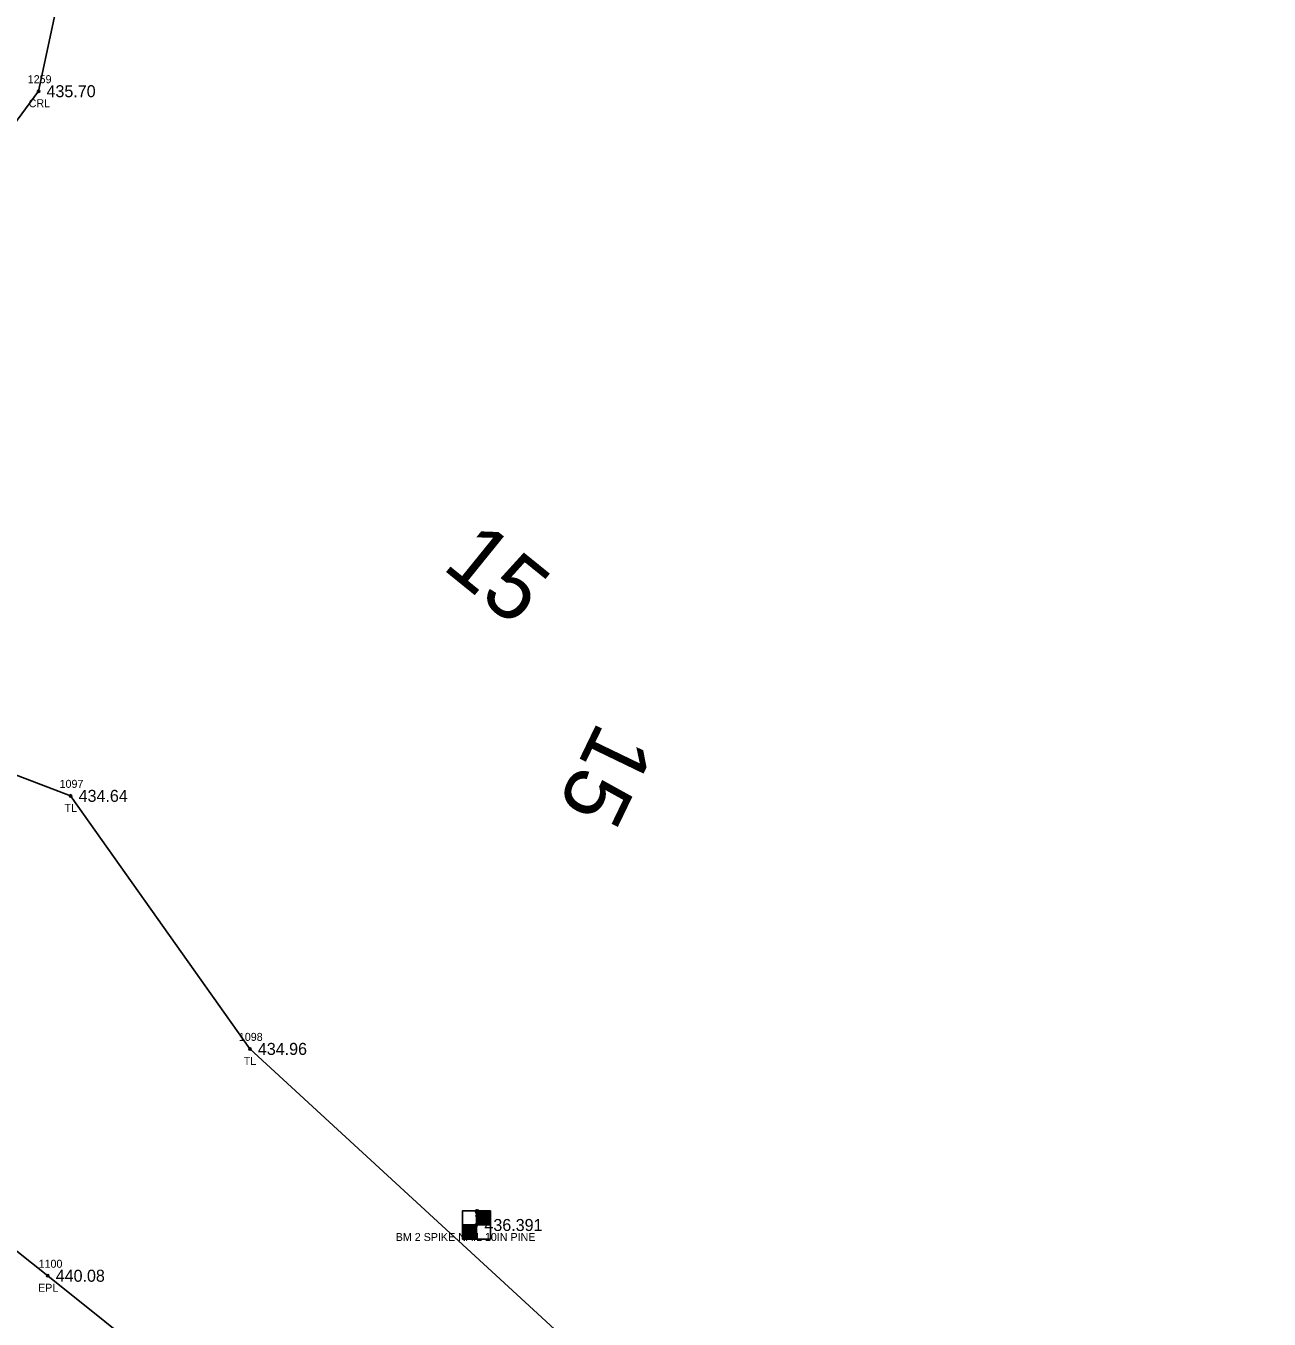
# Model space of a CAD drawing. Extents: x 1611865 to 1617004, y 775289 to 778546.
# Drawn here: x 1614524.5 to 1614679.9, y 777648.2 to 777809.8 of the extents above; entities that cross this region are included whole.
import ezdxf

# ---------------------------------------------------------------- set-up
doc = ezdxf.new("R2010")
doc.units = 0
for name, color, linetype in [('RD_EX_H2O', 7, 'Continuous'), ('RD_EX_H2O_txCode', 7, 'Continuous'), ('RD_EX_Road', 7, 'Continuous'), ('RD_EX_Road_txCode', 7, 'Continuous'), ('RD_EX_TX_H2O_ELEV', 7, 'Continuous'), ('RD_EX_TX_Road_ELEV', 7, 'Continuous'), ('RD_EX_TX_VEG_ELEV', 7, 'Continuous'), ('RD_EX_VEG', 7, 'Continuous'), ('RD_EX_VEG_txCode', 7, 'Continuous'), ('RD_HC_Survey', 7, 'Continuous'), ('RD_HC_Survey_ELEV', 7, 'Continuous'), ('RD_HC_Survey_txCode', 7, 'Continuous'), ('RD_HC_TX_Sta50', 7, 'Continuous'), ('RD_SMD_Locator', 7, 'Continuous')]:
    doc.layers.add(name, color=color, linetype=linetype)

msp = doc.modelspace()

# ---------------------------------------------------------------- linework, layer by layer
at = {"layer": 'RD_EX_H2O'}
msp.add_lwpolyline([(1614612.84, 778001.09), (1614602.8, 777969.59), (1614583.96, 777919.69), (1614574.96, 777902.32), (1614550.82, 777861.38), (1614543.23, 777842.17), (1614528.68, 777813.75), (1614526.1, 777801.65), (1614517.13, 777789.52), (1614510.38, 777774.58), (1614495.52, 777745.97), (1614480.57, 777714.78), (1614474.46, 777705.96), (1614477.93, 777705.13), (1614481.15, 777703.4), (1614481.27, 777700.99), (1614480.97, 777699.74), (1614478.44, 777696.16), (1614475.82, 777697.62), (1614468.32, 777689.25), (1614463.06, 777676.24), (1614459.87, 777668.19), (1614440.89, 777623.61)], dxfattribs=at)
at = {"layer": 'RD_EX_Road'}
msp.add_lwpolyline([(1614484.15, 777687.93), (1614527.25, 777653.67), (1614604.97, 777591.41), (1614629.13, 777572.93), (1614683.14, 777529.85), (1614759.91, 777466.85), (1614838.21, 777403.78), (1614915.19, 777340.18), (1614934.98, 777324.5), (1615070.79, 777214.66)], dxfattribs=at)
at = {"layer": 'RD_EX_VEG'}
msp.add_lwpolyline([(1614491.14, 777728.5), (1614530.11, 777713.62), (1614552.51, 777682.01), (1614626.02, 777614.41), (1614703.99, 777552.85), (1614782.74, 777493.63), (1614860.24, 777426.8), (1615012.81, 777300.37), (1615089.65, 777237.2)], dxfattribs=at)
at = {"layer": 'RD_HC_Survey'}
for p, q in [((1614580.82, 777661.76), (1614580.82, 777658.26)), ((1614580.84, 777661.76), (1614580.84, 777660.01)), ((1614580.87, 777661.76), (1614580.87, 777660.01)), ((1614580.89, 777661.76), (1614580.89, 777660.01)), ((1614580.92, 777661.76), (1614580.92, 777660.01)), ((1614580.94, 777661.76), (1614580.94, 777660.01)), ((1614580.97, 777661.76), (1614580.97, 777660.01)), ((1614580.99, 777661.76), (1614580.99, 777660.01)), ((1614581.01, 777661.76), (1614581.01, 777660.01)), ((1614581.04, 777661.76), (1614581.04, 777660.01)), ((1614581.06, 777661.76), (1614581.06, 777660.01)), ((1614581.09, 777661.76), (1614581.09, 777660.01)), ((1614581.11, 777661.76), (1614581.11, 777660.01)), ((1614581.14, 777661.76), (1614581.14, 777660.01)), ((1614581.16, 777661.76), (1614581.16, 777660.01)), ((1614581.19, 777661.76), (1614581.19, 777660.01)), ((1614581.21, 777661.76), (1614581.21, 777660.01)), ((1614581.24, 777661.76), (1614581.24, 777660.01)), ((1614581.26, 777661.76), (1614581.26, 777660.01)), ((1614581.29, 777661.76), (1614581.29, 777660.01)), ((1614581.31, 777661.76), (1614581.31, 777660.01)), ((1614581.34, 777661.76), (1614581.34, 777660.01)), ((1614581.36, 777661.76), (1614581.36, 777660.01)), ((1614581.39, 777661.76), (1614581.39, 777660.01)), ((1614581.41, 777661.76), (1614581.41, 777660.01)), ((1614581.44, 777661.76), (1614581.44, 777660.01)), ((1614581.46, 777661.76), (1614581.46, 777660.01)), ((1614581.48, 777661.76), (1614581.48, 777660.01)), ((1614581.51, 777661.76), (1614581.51, 777660.01)), ((1614581.53, 777661.76), (1614581.53, 777660.01)), ((1614581.56, 777661.76), (1614581.56, 777660.01)), ((1614581.58, 777661.76), (1614581.58, 777660.01)), ((1614581.61, 777661.76), (1614581.61, 777660.01)), ((1614581.63, 777661.76), (1614581.63, 777660.01)), ((1614581.66, 777661.76), (1614581.66, 777660.01)), ((1614581.68, 777661.76), (1614581.68, 777660.01)), ((1614581.71, 777661.76), (1614581.71, 777660.01)), ((1614581.73, 777661.76), (1614581.73, 777660.01)), ((1614581.76, 777661.76), (1614581.76, 777660.01)), ((1614581.78, 777661.76), (1614581.78, 777660.01)), ((1614581.81, 777661.76), (1614581.81, 777660.01)), ((1614581.83, 777661.76), (1614581.83, 777660.01)), ((1614581.86, 777661.76), (1614581.86, 777660.01)), ((1614581.88, 777661.76), (1614581.88, 777660.01)), ((1614581.91, 777661.76), (1614581.91, 777660.01)), ((1614581.93, 777661.76), (1614581.93, 777660.01)), ((1614581.96, 777661.76), (1614581.96, 777660.01)), ((1614581.98, 777661.76), (1614581.98, 777660.01)), ((1614582, 777661.76), (1614582, 777660.01)), ((1614582.03, 777661.76), (1614582.03, 777660.01)), ((1614582.05, 777661.76), (1614582.05, 777660.01)), ((1614582.08, 777661.76), (1614582.08, 777660.01)), ((1614582.1, 777661.76), (1614582.1, 777660.01)), ((1614582.13, 777661.76), (1614582.13, 777660.01)), ((1614582.15, 777661.76), (1614582.15, 777660.01)), ((1614582.18, 777661.76), (1614582.18, 777660.01)), ((1614582.2, 777661.76), (1614582.2, 777660.01)), ((1614582.23, 777661.76), (1614582.23, 777660.01)), ((1614582.25, 777661.76), (1614582.25, 777660.01)), ((1614582.28, 777661.76), (1614582.28, 777660.01)), ((1614582.3, 777661.76), (1614582.3, 777660.01)), ((1614582.33, 777661.76), (1614582.33, 777660.01)), ((1614582.35, 777661.76), (1614582.35, 777660.01)), ((1614582.38, 777661.76), (1614582.38, 777660.01)), ((1614582.4, 777661.76), (1614582.4, 777660.01)), ((1614582.43, 777661.76), (1614582.43, 777660.01)), ((1614582.45, 777661.76), (1614582.45, 777660.01)), ((1614582.47, 777661.76), (1614582.47, 777660.01)), ((1614582.5, 777661.76), (1614582.5, 777660.01)), ((1614582.52, 777661.76), (1614582.52, 777660.01)), ((1614582.55, 777661.76), (1614582.55, 777660.01)), ((1614582.57, 777660.01), (1614579.07, 777660.01)), ((1614579.07, 777660.01), (1614579.07, 777658.26)), ((1614579.1, 777660.01), (1614579.1, 777658.26)), ((1614579.12, 777660.01), (1614579.12, 777658.26)), ((1614579.15, 777660.01), (1614579.15, 777658.26)), ((1614579.17, 777660.01), (1614579.17, 777658.26)), ((1614579.2, 777660.01), (1614579.2, 777658.26)), ((1614579.22, 777660.01), (1614579.22, 777658.26)), ((1614579.25, 777660.01), (1614579.25, 777658.26)), ((1614579.27, 777660.01), (1614579.27, 777658.26)), ((1614579.3, 777660.01), (1614579.3, 777658.26)), ((1614579.32, 777660.01), (1614579.32, 777658.26)), ((1614579.35, 777660.01), (1614579.35, 777658.26)), ((1614579.37, 777660.01), (1614579.37, 777658.26)), ((1614579.4, 777660.01), (1614579.4, 777658.26)), ((1614579.42, 777660.01), (1614579.42, 777658.26)), ((1614579.45, 777660.01), (1614579.45, 777658.26)), ((1614579.47, 777660.01), (1614579.47, 777658.26)), ((1614579.49, 777660.01), (1614579.49, 777658.26)), ((1614579.52, 777660.01), (1614579.52, 777658.26)), ((1614579.54, 777660.01), (1614579.54, 777658.26)), ((1614579.57, 777660.01), (1614579.57, 777658.26)), ((1614579.59, 777660.01), (1614579.59, 777658.26)), ((1614579.62, 777660.01), (1614579.62, 777658.26)), ((1614579.64, 777660.01), (1614579.64, 777658.26)), ((1614579.67, 777660.01), (1614579.67, 777658.26)), ((1614579.69, 777660.01), (1614579.69, 777658.26)), ((1614579.72, 777660.01), (1614579.72, 777658.26)), ((1614579.74, 777660.01), (1614579.74, 777658.26)), ((1614579.77, 777660.01), (1614579.77, 777658.26)), ((1614579.79, 777660.01), (1614579.79, 777658.26)), ((1614579.82, 777660.01), (1614579.82, 777658.26)), ((1614579.84, 777660.01), (1614579.84, 777658.26)), ((1614579.87, 777660.01), (1614579.87, 777658.26)), ((1614579.89, 777660.01), (1614579.89, 777658.26)), ((1614579.92, 777660.01), (1614579.92, 777658.26)), ((1614579.94, 777660.01), (1614579.94, 777658.26)), ((1614579.96, 777660.01), (1614579.96, 777658.26)), ((1614579.99, 777660.01), (1614579.99, 777658.26)), ((1614580.01, 777660.01), (1614580.01, 777658.26)), ((1614580.04, 777660.01), (1614580.04, 777658.26)), ((1614580.06, 777660.01), (1614580.06, 777658.26)), ((1614580.09, 777660.01), (1614580.09, 777658.26)), ((1614580.11, 777660.01), (1614580.11, 777658.26)), ((1614580.14, 777660.01), (1614580.14, 777658.26)), ((1614580.16, 777660.01), (1614580.16, 777658.26)), ((1614580.19, 777660.01), (1614580.19, 777658.26)), ((1614580.21, 777660.01), (1614580.21, 777658.26)), ((1614580.24, 777660.01), (1614580.24, 777658.26)), ((1614580.26, 777660.01), (1614580.26, 777658.26)), ((1614580.29, 777660.01), (1614580.29, 777658.26)), ((1614580.31, 777660.01), (1614580.31, 777658.26)), ((1614580.34, 777660.01), (1614580.34, 777658.26)), ((1614580.36, 777660.01), (1614580.36, 777658.26)), ((1614580.39, 777660.01), (1614580.39, 777658.26)), ((1614580.41, 777660.01), (1614580.41, 777658.26)), ((1614580.43, 777660.01), (1614580.43, 777658.26)), ((1614580.46, 777660.01), (1614580.46, 777658.26)), ((1614580.48, 777660.01), (1614580.48, 777658.26)), ((1614580.51, 777660.01), (1614580.51, 777658.26)), ((1614580.53, 777660.01), (1614580.53, 777658.26)), ((1614580.56, 777660.01), (1614580.56, 777658.26)), ((1614580.58, 777660.01), (1614580.58, 777658.26)), ((1614580.61, 777660.01), (1614580.61, 777658.26)), ((1614580.63, 777660.01), (1614580.63, 777658.26)), ((1614580.66, 777660.01), (1614580.66, 777658.26)), ((1614580.68, 777660.01), (1614580.68, 777658.26)), ((1614580.71, 777660.01), (1614580.71, 777658.26)), ((1614580.73, 777660.01), (1614580.73, 777658.26)), ((1614580.76, 777660.01), (1614580.76, 777658.26)), ((1614580.78, 777660.01), (1614580.78, 777658.26)), ((1614580.81, 777660.01), (1614580.81, 777658.26))]:
    msp.add_line(p, q, dxfattribs=at)
msp.add_lwpolyline([(1614582.57, 777661.76), (1614579.07, 777661.76), (1614579.07, 777658.26), (1614582.57, 777658.26)], close=True, dxfattribs=at)
at = {"layer": 'RD_SMD_Locator'}
for centre in [(1614526.1, 777801.65), (1614530.11, 777713.62), (1614552.51, 777682.01), (1614580.82, 777660.01), (1614527.25, 777653.67)]:
    msp.add_circle(centre, 0.15, dxfattribs=at)

# ---------------------------------------------------------------- texts
at = {"layer": 'RD_EX_H2O_txCode'}
for s, p in [('1259', (1614524.75, 777802.65)), ('CRL', (1614524.87, 777799.65))]:
    msp.add_text(s, height=1, dxfattribs=at).set_placement(p)
at = {"layer": 'RD_EX_Road_txCode'}
for s, p in [('1100', (1614526.11, 777654.67)), ('EPL', (1614526.04, 777651.67))]:
    msp.add_text(s, height=1, dxfattribs=at).set_placement(p)
at = {"layer": 'RD_EX_TX_H2O_ELEV'}
msp.add_text('435.70', height=1.5, dxfattribs=at).set_placement((1614527.1, 777800.9))
at = {"layer": 'RD_EX_TX_Road_ELEV'}
msp.add_text('440.08', height=1.5, dxfattribs=at).set_placement((1614528.25, 777652.92))
at = {"layer": 'RD_EX_TX_VEG_ELEV'}
for s, p in [('434.64', (1614531.11, 777712.87)), ('434.96', (1614553.51, 777681.26))]:
    msp.add_text(s, height=1.5, dxfattribs=at).set_placement(p)
at = {"layer": 'RD_EX_VEG_txCode'}
for s, p in [('1097', (1614528.73, 777714.62)), ('TL', (1614529.34, 777711.62)), ('1098', (1614551.13, 777683.01)), ('TL', (1614551.74, 777680.01))]:
    msp.add_text(s, height=1, dxfattribs=at).set_placement(p)
at = {"layer": 'RD_HC_Survey_ELEV'}
msp.add_text('436.391', height=1.5, dxfattribs=at).set_placement((1614581.82, 777659.26))
at = {"layer": 'RD_HC_Survey_txCode'}
for s, p in [('9', (1614580.54, 777661.01)), ('BM 2 SPIKE NAIL 10IN PINE', (1614570.73, 777658.01))]:
    msp.add_text(s, height=1, dxfattribs=at).set_placement(p)
at = {"layer": 'RD_HC_TX_Sta50'}
for rotation, p in [(321.0141, (1614576.39, 777742.1)), (244.2484, (1614596.07, 777723.15))]:
    msp.add_text('15', height=8, rotation=rotation, dxfattribs=at).set_placement(p)

doc.saveas('drawing.dxf')
